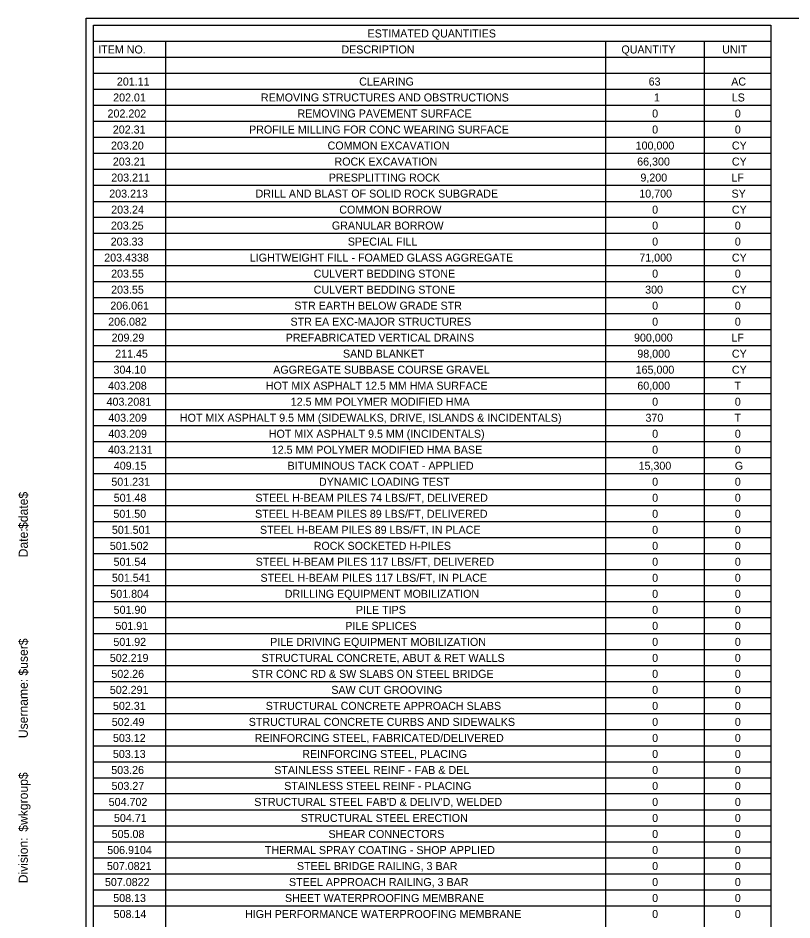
# Model space of a CAD drawing. Extents: x -18.7 to 5.6, y -2.7 to 4.
# Drawn here: x -0.084 to 0.868, y 0.641 to 1.75 of the extents above; entities that cross this region are included whole.
import ezdxf

# ---------------------------------------------------------------- set-up
doc = ezdxf.new("R2010")
doc.units = 0
doc.layers.add('ANNOTATION', color=7, linetype='Continuous')
doc.layers.add('BORDER', color=7, linetype='Continuous')

msp = doc.modelspace()

# ---------------------------------------------------------------- linework, layer by layer
at = {"layer": 'BORDER'}
for p, q in [((0.0088, 1.7215), (0.8421, 1.7215)), ((0.0974, 1.7215), (0.0974, 0.0088)), ((0.6387, 1.7215), (0.6387, 0.0088)), ((0.7601, 1.7215), (0.7601, 0.0088)), ((0.0088, 1.7018), (0.8421, 1.7018)), ((0.0088, 1.6821), (0.8421, 1.6821)), ((0.0088, 1.6624), (0.8421, 1.6624)), ((0.0088, 1.6428), (0.8421, 1.6428)), ((0.0088, 1.6231), (0.8421, 1.6231)), ((0.0088, 1.6034), (0.8421, 1.6034)), ((0.0088, 1.5837), (0.8421, 1.5837)), ((0.0088, 1.564), (0.8421, 1.564)), ((0.0088, 1.5443), (0.8421, 1.5443)), ((0.0088, 1.5246), (0.8421, 1.5246)), ((0.0088, 1.505), (0.8421, 1.505)), ((0.0088, 1.4853), (0.8421, 1.4853)), ((0.0088, 1.4656), (0.8421, 1.4656)), ((0.0088, 1.4459), (0.8421, 1.4459)), ((0.0088, 1.4262), (0.8421, 1.4262)), ((0.0088, 1.4065), (0.8421, 1.4065)), ((0.0088, 1.3868), (0.8421, 1.3868)), ((0.0088, 1.3672), (0.8421, 1.3672)), ((0.0088, 1.3475), (0.8421, 1.3475)), ((0.0088, 1.3278), (0.8421, 1.3278)), ((0.0088, 1.3081), (0.8421, 1.3081)), ((0.0088, 1.2884), (0.8421, 1.2884)), ((0.0088, 1.2687), (0.8421, 1.2687)), ((0.0088, 1.249), (0.8421, 1.249)), ((0.0088, 1.2293), (0.8421, 1.2293)), ((0.0088, 1.2097), (0.8421, 1.2097)), ((0.0088, 1.19), (0.8421, 1.19)), ((0.0088, 1.1703), (0.8421, 1.1703)), ((0.0088, 1.1506), (0.8421, 1.1506)), ((0.0088, 1.1309), (0.8421, 1.1309)), ((0.0088, 1.1112), (0.8421, 1.1112)), ((0.0088, 1.0915), (0.8421, 1.0915)), ((0.0088, 1.0719), (0.8421, 1.0719)), ((0.0088, 1.0522), (0.8421, 1.0522)), ((0.0088, 1.0325), (0.8421, 1.0325)), ((0.0088, 1.0128), (0.8421, 1.0128)), ((0.0088, 0.9931), (0.8421, 0.9931)), ((0.0088, 0.9734), (0.8421, 0.9734)), ((0.0088, 0.9537), (0.8421, 0.9537)), ((0.0088, 0.9341), (0.8421, 0.9341)), ((0.0088, 0.9144), (0.8421, 0.9144)), ((0.0088, 0.8947), (0.8421, 0.8947)), ((0.0088, 0.875), (0.8421, 0.875)), ((0.0088, 0.8553), (0.8421, 0.8553)), ((0.0088, 0.8356), (0.8421, 0.8356)), ((0.0088, 0.8159), (0.8421, 0.8159)), ((0.0088, 0.7963), (0.8421, 0.7963)), ((0.0088, 0.7766), (0.8421, 0.7766)), ((0.0088, 0.7569), (0.8421, 0.7569)), ((0.0088, 0.7372), (0.8421, 0.7372)), ((0.0088, 0.7175), (0.8421, 0.7175)), ((0.0088, 0.6978), (0.8421, 0.6978)), ((0.0088, 0.6781), (0.8421, 0.6781)), ((0.0088, 0.6585), (0.8421, 0.6585))]:
    msp.add_line(p, q, dxfattribs=at)
for points in [[(0, 1.75), (2.6667, 1.75), (2.6667, 0), (0, 0)], [(0.0088, 1.7412), (0.8421, 1.7412), (0.8421, 0.0088), (0.0088, 0.0088)]]:
    msp.add_lwpolyline(points, close=True, dxfattribs=at)

# ---------------------------------------------------------------- texts
at = {"layer": 'ANNOTATION'}
for s, height, p in [('201.11', 0.00984, (0.0377, 1.667)), ('CLEARING', 0.00984, (0.3358, 1.667)), ('63', 0.00984, (0.6919, 1.667)), ('AC', 0.00984, (0.7935, 1.667)), ('202.01', 0.00984, (0.0331, 1.6474)), ('REMOVING STRUCTURES AND OBSTRUCTIONS', 0.009843, (0.2149, 1.6474)), ('1', 0.00984, (0.6984, 1.6474)), ('LS', 0.00984, (0.7941, 1.6474)), ('202.202', 0.00984, (0.0262, 1.6277)), ('REMOVING PAVEMENT SURFACE', 0.009843, (0.2599, 1.6277)), ('0', 0.00984, (0.6962, 1.6277)), ('0', 0.00984, (0.7979, 1.6277)), ('202.31', 0.00984, (0.0327, 1.608)), ('PROFILE MILLING FOR CONC WEARING SURFACE', 0.009843, (0.2003, 1.608)), ('0', 0.00984, (0.6962, 1.608)), ('0', 0.00984, (0.7979, 1.608)), ('203.20', 0.00984, (0.0305, 1.5883)), ('COMMON EXCAVATION', 0.009843, (0.2969, 1.5883)), ('100,000', 0.00984, (0.6759, 1.5883)), ('CY', 0.00984, (0.7943, 1.5883)), ('203.21', 0.00984, (0.0327, 1.5686)), ('ROCK EXCAVATION', 0.009843, (0.3054, 1.5686)), ('66,300', 0.00984, (0.6778, 1.5686)), ('CY', 0.00984, (0.7943, 1.5686)), ('203.211', 0.00984, (0.0308, 1.5489)), ('PRESPLITTING ROCK', 0.009843, (0.2984, 1.5489)), ('9,200', 0.00984, (0.6818, 1.5489)), ('LF', 0.00984, (0.7937, 1.5489)), ('203.213', 0.00984, (0.0283, 1.5292)), ('DRILL AND BLAST OF SOLID ROCK SUBGRADE', 0.009843, (0.2083, 1.5292)), ('10,700', 0.00984, (0.6804, 1.5292)), ('SY', 0.00984, (0.7939, 1.5292)), ('203.24', 0.00984, (0.0307, 1.5095)), ('COMMON BORROW', 0.009843, (0.3113, 1.5095)), ('0', 0.00984, (0.6962, 1.5095)), ('CY', 0.00984, (0.7943, 1.5095)), ('203.25', 0.00984, (0.0304, 1.4899)), ('GRANULAR BORROW', 0.009843, (0.3022, 1.4899)), ('0', 0.00984, (0.6962, 1.4899)), ('0', 0.00984, (0.7979, 1.4899)), ('203.33', 0.00984, (0.0301, 1.4702)), ('SPECIAL FILL', 0.009843, (0.3218, 1.4702)), ('0', 0.00984, (0.6962, 1.4702)), ('0', 0.00984, (0.7979, 1.4702)), ('203.4338', 0.00984, (0.0221, 1.4505)), ('LIGHTWEIGHT FILL - FOAMED GLASS AGGREGATE', 0.009843, (0.2012, 1.4505)), ('71,000', 0.00984, (0.6804, 1.4505)), ('CY', 0.00984, (0.7943, 1.4505)), ('203.55', 0.00984, (0.0306, 1.4308)), ('CULVERT BEDDING STONE', 0.009843, (0.2798, 1.4308)), ('0', 0.00984, (0.6962, 1.4308)), ('0', 0.00984, (0.7979, 1.4308)), ('203.55', 0.00984, (0.0306, 1.4111)), ('CULVERT BEDDING STONE', 0.009843, (0.2798, 1.4111)), ('300', 0.00984, (0.6876, 1.4111)), ('CY', 0.00984, (0.7943, 1.4111)), ('206.061', 0.00984, (0.0296, 1.3914)), ('STR EARTH BELOW GRADE STR', 0.009843, (0.256, 1.3914)), ('0', 0.00984, (0.6962, 1.3914)), ('0', 0.00984, (0.7979, 1.3914)), ('206.082', 0.00984, (0.027, 1.3717)), ('STR EA EXC-MAJOR STRUCTURES', 0.009843, (0.2513, 1.3717)), ('0', 0.00984, (0.6962, 1.3717)), ('0', 0.00984, (0.7979, 1.3717)), ('209.29', 0.00984, (0.0312, 1.3521)), ('PREFABRICATED VERTICAL DRAINS', 0.009843, (0.2454, 1.3521)), ('900,000', 0.00984, (0.6739, 1.3521)), ('LF', 0.00984, (0.7937, 1.3521)), ('211.45', 0.00984, (0.0356, 1.3324)), ('SAND BLANKET', 0.009843, (0.3158, 1.3324)), ('98,000', 0.00984, (0.678, 1.3324)), ('CY', 0.00984, (0.7943, 1.3324)), ('304.10', 0.00984, (0.0335, 1.3127)), ('AGGREGATE SUBBASE COURSE GRAVEL', 0.009843, (0.23, 1.3127)), ('165,000', 0.00984, (0.6759, 1.3127)), ('CY', 0.00984, (0.7943, 1.3127)), ('403.208', 0.00984, (0.0269, 1.293)), ('HOT MIX ASPHALT 12.5 MM HMA SURFACE', 0.009843, (0.2209, 1.293)), ('60,000', 0.00984, (0.678, 1.293)), ('T', 0.00984, (0.7975, 1.293)), ('403.2081', 0.00984, (0.025, 1.2733)), ('12.5 MM POLYMER MODIFIED HMA', 0.009843, (0.2516, 1.2733)), ('0', 0.00984, (0.6962, 1.2733)), ('0', 0.00984, (0.7979, 1.2733)), ('403.209', 0.00984, (0.0271, 1.2536)), ('HOT MIX ASPHALT 9.5 MM (SIDEWALKS, DRIVE, ISLANDS & INCIDENTALS)', 0.009843, (0.1152, 1.2536)), ('370', 0.00984, (0.688, 1.2536)), ('T', 0.00984, (0.7975, 1.2536)), ('403.209', 0.00984, (0.0271, 1.2339)), ('HOT MIX ASPHALT 9.5 MM (INCIDENTALS)', 0.009843, (0.2246, 1.2339)), ('0', 0.00984, (0.6962, 1.2339)), ('0', 0.00984, (0.7979, 1.2339)), ('403.2131', 0.00984, (0.0267, 1.2143)), ('12.5 MM POLYMER MODIFIED HMA BASE', 0.009843, (0.2282, 1.2143)), ('0', 0.00984, (0.6962, 1.2143)), ('0', 0.00984, (0.7979, 1.2143)), ('409.15', 0.00984, (0.0339, 1.1946)), ('BITUMINOUS TACK COAT - APPLIED', 0.009843, (0.2477, 1.1946)), ('15,300', 0.00984, (0.6795, 1.1946)), ('G', 0.00984, (0.7979, 1.1946)), ('501.231', 0.00984, (0.0309, 1.1749)), ('DYNAMIC LOADING TEST', 0.009843, (0.2863, 1.1749)), ('0', 0.00984, (0.6962, 1.1749)), ('0', 0.00984, (0.7979, 1.1749)), ('501.48', 0.00984, (0.0338, 1.1552)), ('STEEL H-BEAM PILES 74 LBS/FT, DELIVERED', 0.009843, (0.2081, 1.1552)), ('0', 0.00984, (0.6962, 1.1552)), ('0', 0.00984, (0.7979, 1.1552)), ('501.50', 0.00984, (0.0334, 1.1355)), ('STEEL H-BEAM PILES 89 LBS/FT, DELIVERED', 0.009843, (0.2077, 1.1355)), ('0', 0.00984, (0.6962, 1.1355)), ('0', 0.00984, (0.7979, 1.1355)), ('501.501', 0.00984, (0.0315, 1.1158)), ('STEEL H-BEAM PILES 89 LBS/FT, IN PLACE', 0.009843, (0.2137, 1.1158)), ('0', 0.00984, (0.6962, 1.1158)), ('0', 0.00984, (0.7979, 1.1158)), ('501.502', 0.00984, (0.029, 1.0961)), ('ROCK SOCKETED H-PILES', 0.009843, (0.2798, 1.0961)), ('0', 0.00984, (0.6962, 1.0961)), ('0', 0.00984, (0.7979, 1.0961)), ('501.54', 0.00984, (0.0336, 1.0765)), ('STEEL H-BEAM PILES 117 LBS/FT, DELIVERED', 0.009843, (0.2084, 1.0765)), ('0', 0.00984, (0.6962, 1.0765)), ('0', 0.00984, (0.7979, 1.0765)), ('501.541', 0.00984, (0.0316, 1.0568)), ('STEEL H-BEAM PILES 117 LBS/FT, IN PLACE', 0.009843, (0.2144, 1.0568)), ('0', 0.00984, (0.6962, 1.0568)), ('0', 0.00984, (0.7979, 1.0568)), ('501.804', 0.00984, (0.0296, 1.0371)), ('DRILLING EQUIPMENT MOBILIZATION', 0.009843, (0.2442, 1.0371)), ('0', 0.00984, (0.6962, 1.0371)), ('0', 0.00984, (0.7979, 1.0371)), ('501.90', 0.00984, (0.0337, 1.0174)), ('PILE TIPS', 0.00984, (0.3318, 1.0174)), ('0', 0.00984, (0.6962, 1.0174)), ('0', 0.00984, (0.7979, 1.0174)), ('501.91', 0.00984, (0.0359, 0.9977)), ('PILE SPLICES', 0.009843, (0.3187, 0.9977)), ('0', 0.00984, (0.6962, 0.9977)), ('0', 0.00984, (0.7979, 0.9977)), ('501.92', 0.00984, (0.0334, 0.978)), ('PILE DRIVING EQUIPMENT MOBILIZATION', 0.009843, (0.2263, 0.978)), ('0', 0.00984, (0.6962, 0.978)), ('0', 0.00984, (0.7979, 0.978)), ('502.219', 0.00984, (0.029, 0.9583)), ('STRUCTURAL CONCRETE, ABUT & RET WALLS', 0.009843, (0.2157, 0.9583)), ('0', 0.00984, (0.6962, 0.9583)), ('0', 0.00984, (0.7979, 0.9583)), ('502.26', 0.00984, (0.0309, 0.9387)), ('STR CONC RD & SW SLABS ON STEEL BRIDGE', 0.009843, (0.2035, 0.9387)), ('0', 0.00984, (0.6962, 0.9387)), ('0', 0.00984, (0.7979, 0.9387)), ('502.291', 0.00984, (0.029, 0.919)), ('SAW CUT GROOVING', 0.009843, (0.3015, 0.919)), ('0', 0.00984, (0.6962, 0.919)), ('0', 0.00984, (0.7979, 0.919)), ('502.31', 0.00984, (0.0329, 0.8993)), ('STRUCTURAL CONCRETE APPROACH SLABS', 0.009843, (0.2208, 0.8993)), ('0', 0.00984, (0.6962, 0.8993)), ('0', 0.00984, (0.7979, 0.8993)), ('502.49', 0.00984, (0.0314, 0.8796)), ('STRUCTURAL CONCRETE CURBS AND SIDEWALKS', 0.009843, (0.1999, 0.8796)), ('0', 0.00984, (0.6962, 0.8796)), ('0', 0.00984, (0.7979, 0.8796)), ('503.12', 0.00984, (0.0329, 0.8599)), ('REINFORCING STEEL, FABRICATED/DELIVERED', 0.009843, (0.2072, 0.8599)), ('0', 0.00984, (0.6962, 0.8599)), ('0', 0.00984, (0.7979, 0.8599)), ('503.13', 0.00984, (0.0328, 0.8402)), ('REINFORCING STEEL, PLACING', 0.009843, (0.2658, 0.8402)), ('0', 0.00984, (0.6962, 0.8402)), ('0', 0.00984, (0.7979, 0.8402)), ('503.26', 0.00984, (0.0308, 0.8205)), ('STAINLESS STEEL REINF - FAB & DEL', 0.009843, (0.2313, 0.8205)), ('0', 0.00984, (0.6962, 0.8205)), ('0', 0.00984, (0.7979, 0.8205)), ('503.27', 0.00984, (0.0311, 0.8009)), ('STAINLESS STEEL REINF - PLACING', 0.009843, (0.2436, 0.8009)), ('0', 0.00984, (0.6962, 0.8009)), ('0', 0.00984, (0.7979, 0.8009)), ('504.702', 0.00984, (0.0276, 0.7812)), ("STRUCTURAL STEEL FAB'D & DELIV'D, WELDED", 0.009843, (0.2067, 0.7812)), ('0', 0.00984, (0.6962, 0.7812)), ('0', 0.00984, (0.7979, 0.7812)), ('504.71', 0.00984, (0.0341, 0.7615)), ('STRUCTURAL STEEL ERECTION', 0.009843, (0.2639, 0.7615)), ('0', 0.00984, (0.6962, 0.7615)), ('0', 0.00984, (0.7979, 0.7615)), ('505.08', 0.00984, (0.0313, 0.7418)), ('SHEAR CONNECTORS', 0.009843, (0.298, 0.7418)), ('0', 0.00984, (0.6962, 0.7418)), ('0', 0.00984, (0.7979, 0.7418)), ('506.9104', 0.00984, (0.0258, 0.7221)), ('THERMAL SPRAY COATING - SHOP APPLIED', 0.009843, (0.2197, 0.7221)), ('0', 0.00984, (0.6962, 0.7221)), ('0', 0.00984, (0.7979, 0.7221)), ('507.0821', 0.00984, (0.0254, 0.7024)), ('STEEL BRIDGE RAILING, 3 BAR', 0.009843, (0.2592, 0.7024)), ('0', 0.00984, (0.6962, 0.7024)), ('0', 0.00984, (0.7979, 0.7024)), ('507.0822', 0.00984, (0.023, 0.6827)), ('STEEL APPROACH RAILING, 3 BAR', 0.009843, (0.2494, 0.6827)), ('0', 0.00984, (0.6962, 0.6827)), ('0', 0.00984, (0.7979, 0.6827)), ('508.13', 0.00984, (0.0332, 0.6631)), ('SHEET WATERPROOFING MEMBRANE', 0.009843, (0.2445, 0.6631)), ('0', 0.00984, (0.6962, 0.6631)), ('0', 0.00984, (0.7979, 0.6631)), ('508.14', 0.00984, (0.0337, 0.6434)), ('HIGH PERFORMANCE WATERPROOFING MEMBRANE', 0.009843, (0.1953, 0.6434)), ('0', 0.00984, (0.6962, 0.6434)), ('0', 0.00984, (0.7979, 0.6434))]:
    msp.add_text(s, height=height, dxfattribs=at).set_placement(p)
at = {"layer": 'BORDER'}
for s, height, p in [('ESTIMATED QUANTITIES', 0.009843, (0.3461, 1.7261)), ('ITEM NO.', 0.00984, (0.0147, 1.7064)), ('DESCRIPTION', 0.009843, (0.3139, 1.7064)), ('QUANTITY', 0.00984, (0.6584, 1.7064)), ('UNIT', 0.00984, (0.7824, 1.7064))]:
    msp.add_text(s, height=height, dxfattribs=at).set_placement(p)
for s, p in [('$date$', (-0.0719, 1.1218)), ('Date:', (-0.0719, 1.0869)), ('$user$', (-0.0719, 0.9415)), ('Username:', (-0.0719, 0.8645)), ('$wkgroup$', (-0.0719, 0.7495)), ('Division:', (-0.0719, 0.6861))]:
    msp.add_text(s, height=0.01116, rotation=90, dxfattribs=at).set_placement(p)

doc.saveas('drawing.dxf')
